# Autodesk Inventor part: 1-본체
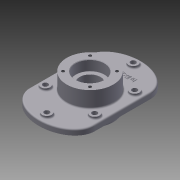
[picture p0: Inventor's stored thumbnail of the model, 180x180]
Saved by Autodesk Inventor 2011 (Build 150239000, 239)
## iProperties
Created: 2015-02
Part Number: 1-본체
Document SubType Name: Modeling
Designer: LINEART07
Density: 2.71 g/cm^3
Material: 알루미늄-6061
Mass: 1658.14 g
Surface Area: 948.023 cm^2
Volume: 611.859 cm^3
Author: LINEART07
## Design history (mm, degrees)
sketch "스케치1"
  geometry: C1 r 50 at (0, 0); 1 further point
  constraints: 1 centre point, 1 coincident
extrude "돌출1" new body sketch "스케치1" distance "d0" = 23; taper "d1" = 0 deg
sketch "스케치2"
  geometry: L1 (0, 0)-(0, 60); L2 (0, 60)-(70, 60); L3 (70, 60)-(-70, 60); L4 (-70, 60)-(-70, -60); L5 (-70, -60)-(70, -60); L6 (70, -60)-(70, 60); L7 (0, 60)-(0, 110); C1 r 50 at (0, 0) reference
  constraints: 14 end point, 3 parallel, 2 perpendicular, 1 horizontal, 1 vertical
extrude "돌출2" join sketch "스케치2" distance "d2" = 12; taper "d3" = 0 deg
sketch "스케치3"
  geometry: C1 r 50 at (0, 0); 1 further point
  constraints: 1 centre point, 1 coincident
extrude "돌출3" join sketch "스케치3" distance "d4" = 35; taper "d5" = 0 deg
sketch "스케치4"
  geometry: C1 r 50 at (0, 0) reference; C2 r 31 at (0, 0)
  constraints: 1 centre point, 1 coincident
extrude "돌출4" cut sketch "스케치4" distance "d6" = 22; taper "d7" = 0 deg
sketch "스케치5"
  geometry: C1 r 50 at (0, 0) reference; C2 r 31 at (0, 0)
  constraints: 1 centre point, 1 coincident
extrude "돌출5" cut sketch "스케치5" distance "d8" = 22; taper "d9" = 0 deg
sketch "스케치6"
  geometry: C1 r 31 at (0, 0) reference; C2 r 22.5 at (0, 0)
  constraints: 1 centre point, 1 coincident
extrude "돌출6" cut sketch "스케치6" stored distance "d10" = 22; taper "d11" = 0 deg
sketch "스케치7"
  geometry: L1 (-70, 60)-(70, 60) reference; L2 (70, -60)-(-70, -60) reference; L3 (0, 60)-(0, 110); L4 (-70, -60)-(-53, -60); L5 (-53, -60)-(-53, 60); L6 (70, -60)-(53, -60); L7 (53, -60)-(53, 60); L8 (0, -60)-(0, -110); 2 further points; 2 other entities
  constraints: 14 end point, 4 point on line, 3 perpendicular, 2 coincident, 2 horizontal, 2 midpoint, 1 vertical, 8 other
extrude "돌출7" join sketch "스케치7" distance "d12" = 12; taper "d13" = 0 deg
sketch "스케치8"
  geometry: L1 (-70, -60)-(-70, 60) reference; L2 (-53, -60)-(-53, 60); L3 (53, 60)-(53, -60); C1 r 10 at (0, 93); C2 r 10 at (0, -93); C3 r 10 at (53, 43); C4 r 10 at (-53, 43); C5 r 10 at (-53, -43); C6 r 10 at (53, -43); 4 further points; 2 other entities
  constraints: 6 centre point, 4 end point, 1 parallel, 1 point on line, 10 other
extrude "돌출8" join sketch "스케치8" distance "d16" = 5; taper "d17" = 0 deg
sketch "스케치9"
  geometry: C1 r 10 at (0, 0) reference; C2 r 10 at (-106, 0) reference; C3 r 10 at (-53, -50) reference; C4 r 10 at (0, 86) reference; C5 r 10 at (-53, 136) reference; C6 r 10 at (-106, 86) reference; C7 r 5.5 at (0, 86); C8 r 5.5 at (0, 0); C9 r 5.5 at (-53, -50); C10 r 5.5 at (-106, 0); C11 r 5.5 at (-106, 86); C12 r 5.5 at (-53, 136); 1 further point
  constraints: 6 centre point, 6 coincident
extrude "돌출9" cut sketch "스케치9" stored distance "d18" = 5; taper "d19" = 0 deg
chamfer "모따기1" distance "d20" = 1; stored, may be unused: second distance "d21" = 2, angle "d22" = 45 deg
fillet "모깎기1" dims "d23" = 0.3
fillet "모깎기2" dims "d24" = 3
sketch "스케치10"
  geometry: L1 (0, 0)-(28.991, 28.991); L2 (-1.975, -1.975)-(-28.991, -28.991); L3 (0, 0)-(28.991, -28.991); L4 (0, 0)-(-28.991, 28.991); C1 r 32 at (0, 0) reference; A1 r 41 centre (0, 0) between (28.991, 28.991) and (-28.991, -28.991); 4 further points
  constraints: 8 end point, 5 coincident, 4 point on circle, 2 collinear, 1 centre point, 1 perpendicular
hole "Hole1" sketch "스케치10" at (-28.991, 28.991), (-28.991, -28.991), (28.991, -28.991), (28.991, 28.991) diameter "d25" = 6.401; stored, may be unused: countersink angle "d29" = 90 deg, drill point angle "d31" = 118 deg; dims "d26" = 10, "d27" = 4, "d28" = 2, "d30" = 13
sketch "스케치11"
  geometry: C1 r 3.2 at (-28.991, 28.991) reference; C2 r 3.2 at (28.991, 28.991) reference; C3 r 50 at (0, 0) reference; C4 r 32 at (0, 0) reference; C5 r 3.2 at (28.991, -28.991) reference; C6 r 3.2 at (-28.991, -28.991) reference; 4 further points
  constraints: 4 coincident
hole "Hole2" sketch "스케치11" at (-28.991, 28.991), (-28.991, -28.991), (28.991, -28.991), (28.991, 28.991) diameter "d32" = 6.401; stored, may be unused: countersink angle "d36" = 90 deg, drill point angle "d38" = 118 deg; dims "d33" = 10, "d34" = 4, "d35" = 2, "d37" = 13
sketch "스케치12"
  geometry: L1 (-67, -60)-(-67, 60) reference; L2 (0, 0)-(0, 65); L3 (-55.717, 71.822)-(56.671, 71.822); L4 (56.671, 71.822)-(56.671, 58.825); L5 (56.671, 58.825)-(-55.717, 58.825); L6 (-55.717, 58.825)-(-55.717, 71.822); C1 r 53 at (0, 0) reference
  constraints: 2 end point, 1 parallel, 2 other
extrude "돌출10" join sketch "스케치12" distance "d39" = 1; taper "d40" = 0 deg
node "솔리드1"
node "투영된 루프1"
node "투영된 루프2"
node "투영된 루프3"
node "투영된 루프4"
node "투영된 루프5"
node "투영된 루프6"
